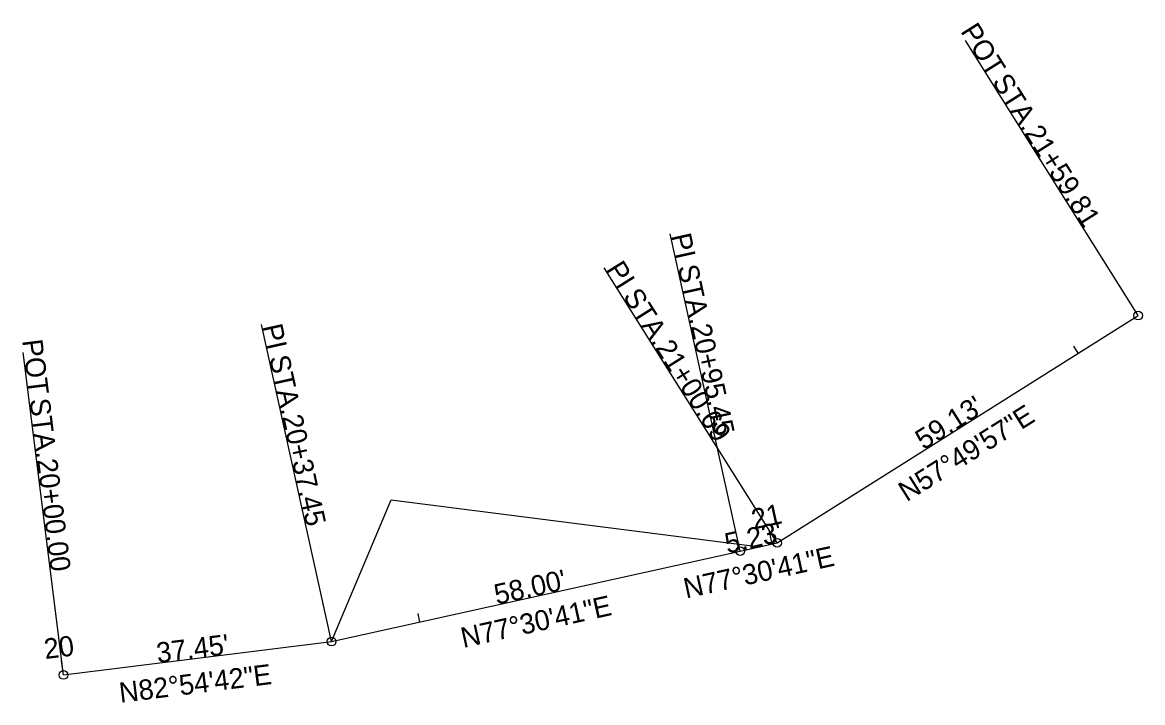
# Model space of a CAD drawing. Extents: x 2314372 to 2314527, y 564815 to 564909.
import ezdxf

# ---------------------------------------------------------------- set-up
doc = ezdxf.new("R2010")
doc.units = 0
for name, color, linetype in [('GE_P_Alignment', 7, 'Continuous'), ('GE_P_Alignment_100_Bearings', 7, 'Continuous'), ('GE_P_Alignment_100_Cardinal_Points', 7, 'Continuous'), ('GE_P_Alignment_100_Distances', 7, 'Continuous'), ('GE_P_Alignment_100_Stations', 7, 'Continuous'), ('SC_Scratch1', 7, 'Continuous')]:
    doc.layers.add(name, color=color, linetype=linetype)

msp = doc.modelspace()

# ---------------------------------------------------------------- linework, layer by layer
at = {"layer": 'GE_P_Alignment'}
for p, q in [((2314476.76, 564837.11), (2314526.81, 564868.59)), ((2314471.65, 564835.98), (2314476.76, 564837.11)), ((2314415.03, 564823.44), (2314471.65, 564835.98)), ((2314377.86, 564818.82), (2314415.03, 564823.44))]:
    msp.add_line(p, q, dxfattribs=at)
at = {"layer": 'GE_P_Alignment_100_Cardinal_Points'}
for p, q in [((2314526.81, 564868.59), (2314502.85, 564906.68)), ((2314471.65, 564835.98), (2314461.92, 564879.91)), ((2314476.76, 564837.11), (2314452.8, 564875.2)), ((2314415.03, 564823.44), (2314405.29, 564867.37)), ((2314377.86, 564818.82), (2314372.3, 564863.47))]:
    msp.add_line(p, q, dxfattribs=at)
for centre in [(2314526.81, 564868.59), (2314476.76, 564837.11), (2314471.65, 564835.98), (2314415.03, 564823.44), (2314377.86, 564818.82)]:
    msp.add_circle(centre, 0.6, dxfattribs=at)
at = {"layer": 'GE_P_Alignment_100_Stations'}
for p, q in [((2314518.5, 564863.37), (2314517.87, 564864.38)), ((2314476.09, 564836.96), (2314475.66, 564838.92)), ((2314427.27, 564826.15), (2314427.01, 564827.32)), ((2314377.86, 564818.82), (2314377.61, 564820.8))]:
    msp.add_line(p, q, dxfattribs=at)
at = {"layer": 'SC_Scratch1'}
for p, q in [((2314415.03, 564823.44), (2314423.29, 564843.06)), ((2314423.29, 564843.06), (2314474.35, 564836.58))]:
    msp.add_line(p, q, dxfattribs=at)

# ---------------------------------------------------------------- texts
at = {"layer": 'GE_P_Alignment_100_Bearings'}
for s, rotation, p in [('N57°49\'57"E', 32.1675, (2314494.72, 564842.74)), ('N77°30\'41"E', 12.4887, (2314464.15, 564829.4)), ('N77°30\'41"E', 12.4887, (2314433.28, 564822.56)), ('N82°54\'42"E', 7.0884, (2314385.76, 564814.96))]:
    msp.add_text(s, height=2.8, rotation=rotation, dxfattribs=at).set_placement(p)
at = {"layer": 'GE_P_Alignment_100_Cardinal_Points'}
for s, rotation, p in [('POT', 302.1675, (2314502.1, 564907.96)), (' STA. ', 302.1675, (2314505.93, 564901.87)), ('21+59.81', 302.1675, (2314510.96, 564893.87)), ('PI', 282.4887, (2314462.02, 564879.67)), ('PI', 302.1675, (2314452.97, 564875.01)), (' STA. ', 282.4887, (2314462.75, 564876.35)), (' STA. ', 302.1675, (2314454.78, 564872.14)), ('PI', 282.4887, (2314405.39, 564867.12)), ('20+95.45', 282.4887, (2314464.8, 564867.13)), ('POT', 277.0884, (2314372.14, 564865.15)), ('21+00.69', 302.1675, (2314459.81, 564864.14)), (' STA. ', 282.4887, (2314406.13, 564863.81)), (' STA. ', 277.0884, (2314373.03, 564858)), ('20+37.45', 282.4887, (2314408.17, 564854.58)), ('20+00.00', 277.0884, (2314374.19, 564848.62))]:
    msp.add_text(s, height=2.8, rotation=rotation, dxfattribs=at).set_placement(p)
at = {"layer": 'GE_P_Alignment_100_Distances'}
for s, rotation, p in [("59.13'", 32.1675, (2314497.06, 564849.92)), ("5.23'", 12.4887, (2314469.86, 564835.63)), ("58.00'", 12.4887, (2314437.9, 564828.55)), ("37.45'", 7.0884, (2314390.92, 564820.48))]:
    msp.add_text(s, height=2.8, rotation=rotation, dxfattribs=at).set_placement(p)
at = {"layer": 'GE_P_Alignment_100_Stations'}
for s, rotation, p in [('21', 12.4887, (2314473.56, 564838.96)), ('20', 7.0884, (2314375.34, 564821.02))]:
    msp.add_text(s, height=2.8, rotation=rotation, dxfattribs=at).set_placement(p)

doc.saveas('drawing.dxf')
